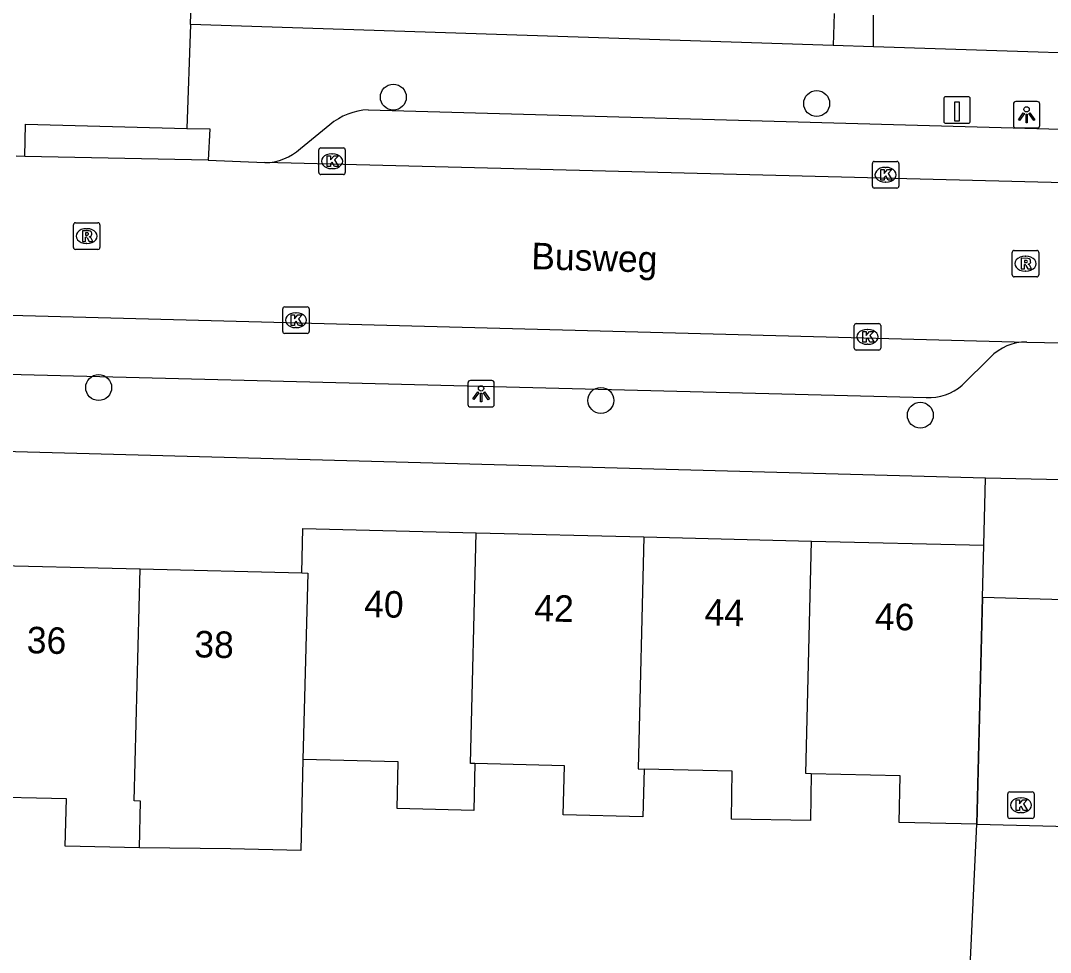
# Model space of a CAD drawing. Extents: x 162082 to 163393, y 388091 to 388632.
# Drawn here: x 162430.78 to 162469.63, y 388296.46 to 388331.61 of the extents above; entities that cross this region are included whole.
import ezdxf

# ---------------------------------------------------------------- set-up
doc = ezdxf.new("R2010")
doc.units = 0
for name, color, linetype in [('IMGEO_Boom', 7, 'Continuous'), ('IMGEO_Kolk', 7, 'Continuous'), ('IMGEO_Laadpaal', 7, 'Continuous'), ('IMGEO_Lichtpunt', 7, 'Continuous'), ('IMGEO_Muur', 7, 'Continuous'), ('IMGEO_Openbare_ruimte_label', 7, 'Continuous'), ('IMGEO_Pand', 7, 'Continuous'), ('IMGEO_Pand_nummerreeks', 7, 'Continuous'), ('IMGEO_Pand_overbouw', 7, 'Continuous'), ('IMGEO_Rijbaan_lokaal_open', 7, 'Continuous'), ('IMGEO_Rioolput', 7, 'Continuous'), ('IMGEO_Voetpad_open', 7, 'Continuous')]:
    doc.layers.add(name, color=color, linetype=linetype)

msp = doc.modelspace()

# ---------------------------------------------------------------- linework, layer by layer
at = {"layer": 'IMGEO_Boom'}
for centre in [(162444.844, 388328.725), (162460.816, 388328.485), (162433.728, 388317.767), (162452.674, 388317.284), (162464.726, 388316.726)]:
    msp.add_circle(centre, 0.489, dxfattribs=at)
at = {"layer": 'IMGEO_Kolk'}
for p, q in [((162442.032, 388325.881), (162442.032, 388326.733)), ((162442.107, 388326.807), (162442.959, 388326.807)), ((162443.033, 388326.733), (162443.033, 388325.881)), ((162442.52, 388326.587), (162442.545, 388326.587)), ((162462.991, 388326.297), (162463.843, 388326.297)), ((162442.543, 388326.027), (162442.518, 388326.027)), ((162462.916, 388325.371), (162462.916, 388326.223)), ((162463.404, 388326.077), (162463.429, 388326.077)), ((162463.917, 388326.223), (162463.917, 388325.371)), ((162442.959, 388325.807), (162442.107, 388325.807)), ((162463.843, 388325.297), (162462.991, 388325.297)), ((162463.427, 388325.517), (162463.402, 388325.517)), ((162440.671, 388319.884), (162440.671, 388320.736)), ((162440.746, 388320.81), (162441.598, 388320.81)), ((162441.159, 388320.59), (162441.184, 388320.59)), ((162441.672, 388320.736), (162441.672, 388319.884)), ((162462.234, 388319.254), (162462.234, 388320.106)), ((162462.309, 388320.18), (162463.161, 388320.18)), ((162463.235, 388320.106), (162463.235, 388319.254)), ((162441.598, 388319.81), (162440.746, 388319.81)), ((162441.182, 388320.03), (162441.157, 388320.03)), ((162462.722, 388319.96), (162462.747, 388319.96)), ((162462.745, 388319.4), (162462.72, 388319.4)), ((162463.161, 388319.18), (162462.309, 388319.18)), ((162468.023, 388301.586), (162468.023, 388302.438)), ((162468.098, 388302.512), (162468.95, 388302.512)), ((162468.511, 388302.292), (162468.536, 388302.292)), ((162469.024, 388302.438), (162469.024, 388301.586)), ((162468.95, 388301.512), (162468.098, 388301.512)), ((162468.534, 388301.732), (162468.509, 388301.732))]:
    msp.add_line(p, q, dxfattribs=at)
for points in [[(162442.032, 388325.881), (162442.032, 388326.733)], [(162442.107, 388326.807), (162442.959, 388326.807)], [(162443.033, 388326.733), (162443.033, 388325.881)], [(162442.353, 388326.507), (162442.476, 388326.507), (162442.476, 388326.356), (162442.606, 388326.507), (162442.77, 388326.507), (162442.624, 388326.356), (162442.777, 388326.107), (162442.625, 388326.107), (162442.54, 388326.271), (162442.476, 388326.204), (162442.476, 388326.107), (162442.353, 388326.107), (162442.353, 388326.507)], [(162462.991, 388326.297), (162463.843, 388326.297)], [(162462.916, 388325.371), (162462.916, 388326.223)], [(162463.237, 388325.997), (162463.36, 388325.997), (162463.36, 388325.846), (162463.49, 388325.997), (162463.654, 388325.997), (162463.508, 388325.846), (162463.661, 388325.597), (162463.509, 388325.597), (162463.424, 388325.761), (162463.36, 388325.694), (162463.36, 388325.597), (162463.237, 388325.597), (162463.237, 388325.997)], [(162463.917, 388326.223), (162463.917, 388325.371)], [(162442.959, 388325.807), (162442.107, 388325.807)], [(162463.843, 388325.297), (162462.991, 388325.297)], [(162440.671, 388319.884), (162440.671, 388320.736)], [(162440.746, 388320.81), (162441.598, 388320.81)], [(162440.992, 388320.51), (162441.115, 388320.51), (162441.115, 388320.359), (162441.245, 388320.51), (162441.409, 388320.51), (162441.263, 388320.359), (162441.416, 388320.11), (162441.264, 388320.11), (162441.179, 388320.274), (162441.115, 388320.207), (162441.115, 388320.11), (162440.992, 388320.11), (162440.992, 388320.51)], [(162441.672, 388320.736), (162441.672, 388319.884)], [(162462.234, 388319.254), (162462.234, 388320.106)], [(162462.309, 388320.18), (162463.161, 388320.18)], [(162463.235, 388320.106), (162463.235, 388319.254)], [(162441.598, 388319.81), (162440.746, 388319.81)], [(162462.555, 388319.88), (162462.678, 388319.88), (162462.678, 388319.729), (162462.808, 388319.88), (162462.972, 388319.88), (162462.826, 388319.729), (162462.979, 388319.48), (162462.827, 388319.48), (162462.742, 388319.644), (162462.678, 388319.577), (162462.678, 388319.48), (162462.555, 388319.48), (162462.555, 388319.88)], [(162463.161, 388319.18), (162462.309, 388319.18)], [(162468.023, 388301.586), (162468.023, 388302.438)], [(162468.098, 388302.512), (162468.95, 388302.512)], [(162468.344, 388302.212), (162468.467, 388302.212), (162468.467, 388302.061), (162468.597, 388302.212), (162468.761, 388302.212), (162468.615, 388302.061), (162468.768, 388301.812), (162468.616, 388301.812), (162468.531, 388301.976), (162468.467, 388301.909), (162468.467, 388301.812), (162468.344, 388301.812), (162468.344, 388302.212)], [(162469.024, 388302.438), (162469.024, 388301.586)], [(162468.95, 388301.512), (162468.098, 388301.512)]]:
    msp.add_lwpolyline(points, dxfattribs=at)
for centre, start, end in [((162442.109, 388326.731), 91.552, 178.448), ((162442.109, 388326.731), 91.552, 178.448), ((162442.957, 388326.731), 1.552, 88.448), ((162442.957, 388326.731), 1.552, 88.448), ((162462.993, 388326.221), 91.552, 178.448), ((162462.993, 388326.221), 91.552, 178.448), ((162463.841, 388326.221), 1.552, 88.448), ((162463.841, 388326.221), 1.552, 88.448), ((162442.109, 388325.883), 181.552, 268.448), ((162442.109, 388325.883), 181.552, 268.448), ((162442.957, 388325.883), 271.552, 358.448), ((162442.957, 388325.883), 271.552, 358.448), ((162462.993, 388325.373), 181.552, 268.448), ((162462.993, 388325.373), 181.552, 268.448), ((162463.841, 388325.373), 271.552, 358.448), ((162463.841, 388325.373), 271.552, 358.448), ((162440.748, 388320.734), 91.552, 178.448), ((162440.748, 388320.734), 91.552, 178.448), ((162441.596, 388320.734), 1.552, 88.448), ((162441.596, 388320.734), 1.552, 88.448), ((162462.311, 388320.104), 91.552, 178.448), ((162462.311, 388320.104), 91.552, 178.448), ((162463.159, 388320.104), 1.552, 88.448), ((162463.159, 388320.104), 1.552, 88.448), ((162440.748, 388319.886), 181.552, 268.448), ((162440.748, 388319.886), 181.552, 268.448), ((162441.596, 388319.886), 271.552, 358.448), ((162441.596, 388319.886), 271.552, 358.448), ((162462.311, 388319.256), 181.552, 268.448), ((162462.311, 388319.256), 181.552, 268.448), ((162463.159, 388319.256), 271.552, 358.448), ((162463.159, 388319.256), 271.552, 358.448), ((162468.1, 388302.436), 91.552, 178.448), ((162468.1, 388302.436), 91.552, 178.448), ((162468.948, 388302.436), 1.552, 88.448), ((162468.948, 388302.436), 1.552, 88.448), ((162468.1, 388301.588), 181.552, 268.448), ((162468.1, 388301.588), 181.552, 268.448), ((162468.948, 388301.588), 271.552, 358.448), ((162468.948, 388301.588), 271.552, 358.448)]:
    msp.add_arc(centre, 0.0765, start, end, dxfattribs=at)
for centre, major_axis, ratio, start_param, end_param in [((162442.519, 388326.307), (-0.387, 0.002), 0.722429, 4.712389, 7.853982), ((162442.544, 388326.307), (-0.39, 0.002), 0.717154, 1.570796, 4.712389), ((162463.403, 388325.797), (-0.387, 0.002), 0.722429, 4.712389, 7.853982), ((162463.428, 388325.797), (-0.39, 0.002), 0.717154, 1.570796, 4.712389), ((162441.158, 388320.31), (-0.387, 0.002), 0.722429, 4.712389, 7.853982), ((162441.183, 388320.31), (-0.39, 0.002), 0.717154, 1.570796, 4.712389), ((162462.721, 388319.68), (-0.387, 0.002), 0.722429, 4.712389, 7.853982), ((162462.746, 388319.68), (-0.39, 0.002), 0.717154, 1.570796, 4.712389), ((162468.51, 388302.012), (-0.387, 0.002), 0.722429, 4.712389, 7.853982), ((162468.535, 388302.012), (-0.39, 0.002), 0.717154, 1.570796, 4.712389)]:
    msp.add_ellipse(centre, major_axis=major_axis, ratio=ratio, start_param=start_param, end_param=end_param, dxfattribs=at)
at = {"layer": 'IMGEO_Laadpaal'}
for p, q in [((162465.611, 388328.655), (162465.611, 388327.814)), ((162465.611, 388328.655), (162465.611, 388327.814)), ((162466.527, 388328.739), (162465.686, 388328.739)), ((162466.527, 388328.739), (162465.686, 388328.739)), ((162466.611, 388327.823), (162466.611, 388328.664)), ((162466.611, 388327.823), (162466.611, 388328.664)), ((162465.695, 388327.739), (162466.536, 388327.739)), ((162465.695, 388327.739), (162466.536, 388327.739))]:
    msp.add_line(p, q, dxfattribs=at)
msp.add_lwpolyline([(162466.026, 388328.552), (162466.186, 388328.552), (162466.186, 388327.819), (162466.026, 388327.819), (162466.026, 388328.552)], dxfattribs=at)
for centre, start, end in [((162465.689, 388328.661), 92.4484, 184.2845), ((162465.689, 388328.661), 92.4484, 184.2845), ((162466.533, 388328.661), 2.4484, 94.2845), ((162466.533, 388328.661), 2.4484, 94.2845), ((162465.689, 388327.817), 182.4484, 274.2845), ((162465.689, 388327.817), 182.4484, 274.2845), ((162466.533, 388327.817), 272.4484, 4.2845), ((162466.533, 388327.817), 272.4484, 4.2845)]:
    msp.add_arc(centre, 0.0779, start, end, dxfattribs=at)
at = {"layer": 'IMGEO_Lichtpunt'}
for p, q in [((162468.238, 388328.467), (162468.238, 388327.66)), ((162468.238, 388328.467), (162468.238, 388327.66)), ((162469.14, 388328.562), (162468.332, 388328.562)), ((162469.14, 388328.562), (162468.332, 388328.562)), ((162469.234, 388327.66), (162469.234, 388328.467)), ((162469.234, 388327.66), (162469.234, 388328.467)), ((162468.332, 388327.566), (162469.14, 388327.566)), ((162468.332, 388327.566), (162469.14, 388327.566)), ((162447.656, 388317.938), (162447.656, 388317.131)), ((162447.656, 388317.938), (162447.656, 388317.131)), ((162448.558, 388318.033), (162447.75, 388318.033)), ((162448.558, 388318.033), (162447.75, 388318.033)), ((162448.652, 388317.131), (162448.652, 388317.938)), ((162448.652, 388317.131), (162448.652, 388317.938)), ((162447.75, 388317.037), (162448.558, 388317.037)), ((162447.75, 388317.037), (162448.558, 388317.037))]:
    msp.add_line(p, q, dxfattribs=at)
for points in [[(162468.612, 388328.131), (162468.651, 388328.103), (162468.463, 388327.841), (162468.425, 388327.868), (162468.612, 388328.131)], [(162468.714, 388328.083), (162468.761, 388328.083), (162468.761, 388327.761), (162468.714, 388327.761), (162468.714, 388328.083)], [(162468.824, 388328.103), (162468.862, 388328.13), (162469.049, 388327.868), (162469.01, 388327.84), (162468.824, 388328.103)], [(162448.03, 388317.602), (162448.069, 388317.574), (162447.881, 388317.312), (162447.843, 388317.339), (162448.03, 388317.602)], [(162448.132, 388317.554), (162448.179, 388317.554), (162448.179, 388317.232), (162448.132, 388317.232), (162448.132, 388317.554)], [(162448.242, 388317.574), (162448.28, 388317.601), (162448.467, 388317.339), (162448.428, 388317.311), (162448.242, 388317.574)]]:
    msp.add_lwpolyline(points, dxfattribs=at)
for centre in [(162468.737, 388328.265), (162448.155, 388317.736)]:
    msp.add_circle(centre, 0.0994, dxfattribs=at)
for centre, start, end in [((162468.332, 388328.467), 90, 180), ((162468.332, 388328.467), 90, 180), ((162469.14, 388328.467), 0, 90), ((162469.14, 388328.467), 0, 90), ((162468.332, 388327.66), 180, 270), ((162468.332, 388327.66), 180, 270), ((162469.14, 388327.66), 270, 0), ((162469.14, 388327.66), 270, 360), ((162447.75, 388317.938), 90, 180), ((162447.75, 388317.938), 90, 180), ((162448.558, 388317.938), 0, 90), ((162448.558, 388317.938), 0, 90), ((162447.75, 388317.131), 180, 270), ((162447.75, 388317.131), 180, 270), ((162448.558, 388317.131), 270, 0), ((162448.558, 388317.131), 270, 360)]:
    msp.add_arc(centre, 0.0946, start, end, dxfattribs=at)
at = {"layer": 'IMGEO_Muur'}
msp.add_lwpolyline([(162466.603, 388295.92), (162466.861, 388301.293)], dxfattribs=at)
at = {"layer": 'IMGEO_Pand'}
for points in [[(162441.388, 388310.774), (162441.429, 388312.454), (162447.975, 388312.292)], [(162447.921, 388303.581), (162447.758, 388303.585), (162447.975, 388312.292)], [(162447.975, 388312.292), (162454.298, 388312.135)], [(162454.298, 388312.135), (162454.08, 388303.378), (162454.304, 388303.372)], [(162454.298, 388312.135), (162460.621, 388311.979)], [(162460.602, 388303.199), (162460.403, 388303.204), (162460.621, 388311.979)], [(162460.621, 388311.979), (162467.122, 388311.818)], [(162466.861, 388301.293), (162467.073, 388309.842), (162467.122, 388311.818)], [(162428.957, 388311.082), (162435.287, 388310.925)], [(162435.265, 388300.402), (162435.308, 388302.169), (162435.07, 388302.175), (162435.287, 388310.925)], [(162435.287, 388310.925), (162441.388, 388310.774)], [(162441.388, 388310.774), (162441.613, 388310.769), (162441.435, 388303.738)], [(162441.435, 388303.738), (162441.35, 388300.301), (162438.703, 388300.367), (162435.265, 388300.402)], [(162447.921, 388303.581), (162447.877, 388301.814), (162444.984, 388301.885), (162445.028, 388303.649), (162441.435, 388303.738)], [(162454.304, 388303.372), (162454.259, 388301.579), (162451.25, 388301.653), (162451.296, 388303.498), (162447.921, 388303.581)], [(162460.602, 388303.199), (162460.582, 388301.439), (162457.608, 388301.486), (162457.624, 388303.29), (162454.304, 388303.372)], [(162466.861, 388301.293), (162463.927, 388301.365), (162463.971, 388303.116), (162460.602, 388303.199)], [(162435.265, 388300.402), (162432.469, 388300.471), (162432.513, 388302.247), (162429.089, 388302.332)]]:
    msp.add_lwpolyline(points, dxfattribs=at)
at = {"layer": 'IMGEO_Pand_overbouw'}
msp.add_lwpolyline([(162470.337, 388301.204), (162470.557, 388309.753), (162467.073, 388309.842), (162466.861, 388301.293)], close=True, dxfattribs=at)
at = {"layer": 'IMGEO_Rijbaan_lokaal_open'}
for points in [[(162430.947, 388326.484), (162430.617, 388326.496)], [(162437.864, 388326.35), (162430.947, 388326.484)], [(162437.864, 388326.35), (162439.995, 388326.254)], [(162473.121, 388325.423), (162439.995, 388326.254)], [(162408.612, 388321.073), (162468.742, 388319.487)], [(162468.742, 388319.487), (162472.729, 388319.405)]]:
    msp.add_lwpolyline(points, dxfattribs=at)
at = {"layer": 'IMGEO_Rioolput'}
for p, q in [((162432.85, 388323.983), (162433.702, 388323.983)), ((162432.775, 388323.057), (162432.775, 388323.909)), ((162433.263, 388323.763), (162433.288, 388323.763)), ((162433.776, 388323.909), (162433.776, 388323.057)), ((162433.286, 388323.203), (162433.261, 388323.203)), ((162433.702, 388322.983), (162432.85, 388322.983)), ((162468.193, 388322.018), (162468.193, 388322.87)), ((162468.268, 388322.944), (162469.12, 388322.944)), ((162469.194, 388322.87), (162469.194, 388322.018)), ((162468.681, 388322.724), (162468.706, 388322.724)), ((162468.704, 388322.164), (162468.679, 388322.164)), ((162469.12, 388321.944), (162468.268, 388321.944))]:
    msp.add_line(p, q, dxfattribs=at)
for points in [[(162432.85, 388323.983), (162433.702, 388323.983)], [(162432.775, 388323.057), (162432.775, 388323.909)], [(162433.364, 388323.681), (162433.112, 388323.683), (162433.112, 388323.283)], [(162433.29, 388323.602), (162433.236, 388323.602), (162433.236, 388323.521)], [(162433.776, 388323.909), (162433.776, 388323.057)], [(162433.112, 388323.283), (162433.236, 388323.283), (162433.236, 388323.445), (162433.247, 388323.445)], [(162433.236, 388323.521), (162433.288, 388323.521)], [(162433.294, 388323.416), (162433.365, 388323.283), (162433.505, 388323.283), (162433.44, 388323.409)], [(162433.702, 388322.983), (162432.85, 388322.983)], [(162468.193, 388322.018), (162468.193, 388322.87)], [(162468.268, 388322.944), (162469.12, 388322.944)], [(162469.194, 388322.87), (162469.194, 388322.018)], [(162468.782, 388322.642), (162468.53, 388322.644), (162468.53, 388322.244)], [(162468.708, 388322.563), (162468.654, 388322.563), (162468.654, 388322.482)], [(162468.654, 388322.482), (162468.706, 388322.482)], [(162468.53, 388322.244), (162468.654, 388322.244), (162468.654, 388322.406), (162468.665, 388322.406)], [(162468.712, 388322.377), (162468.783, 388322.244), (162468.923, 388322.244), (162468.858, 388322.37)], [(162469.12, 388321.944), (162468.268, 388321.944)]]:
    msp.add_lwpolyline(points, dxfattribs=at)
for centre, radius, start, end in [((162432.852, 388323.907), 0.0765, 91.552, 178.448), ((162432.852, 388323.907), 0.0765, 91.552, 178.448), ((162433.7, 388323.907), 0.0765, 1.552, 88.448), ((162433.7, 388323.907), 0.0765, 1.552, 88.448), ((162433.296, 388323.506), 0.0964, 77.0061, 93.1865), ((162433.31, 388323.563), 0.0378, 276.6634, 79.6772), ((162433.363, 388323.571), 0.109, 350.3612, 89.416), ((162433.246, 388323.392), 0.0533, 26.0293, 88.6989), ((162433.272, 388323.71), 0.19, 274.7715, 282.9687), ((162433.361, 388323.571), 0.112, 277.5842, 350.9817), ((162433.345, 388323.356), 0.108, 29.5134, 73.7905), ((162432.852, 388323.059), 0.0765, 181.552, 268.448), ((162432.852, 388323.059), 0.0765, 181.552, 268.448), ((162433.7, 388323.059), 0.0765, 271.552, 358.448), ((162433.7, 388323.059), 0.0765, 271.552, 358.448), ((162468.27, 388322.868), 0.0765, 91.552, 178.448), ((162468.27, 388322.868), 0.0765, 91.552, 178.448), ((162469.118, 388322.868), 0.0765, 1.552, 88.448), ((162469.118, 388322.868), 0.0765, 1.552, 88.448), ((162468.69, 388322.671), 0.19, 274.7715, 282.9687), ((162468.714, 388322.467), 0.0964, 77.0061, 93.1865), ((162468.728, 388322.524), 0.0378, 276.6634, 79.6772), ((162468.781, 388322.532), 0.109, 350.3612, 89.416), ((162468.779, 388322.532), 0.112, 277.5842, 350.9817), ((162468.763, 388322.317), 0.108, 29.5134, 73.7905), ((162468.664, 388322.353), 0.0533, 26.0293, 88.6989), ((162468.27, 388322.02), 0.0765, 181.552, 268.448), ((162468.27, 388322.02), 0.0765, 181.552, 268.448), ((162469.118, 388322.02), 0.0765, 271.552, 358.448), ((162469.118, 388322.02), 0.0765, 271.552, 358.448)]:
    msp.add_arc(centre, radius, start, end, dxfattribs=at)
for centre, major_axis, ratio, start_param, end_param in [((162433.262, 388323.483), (-0.387, 0.002), 0.722429, 4.712389, 7.853982), ((162433.287, 388323.483), (-0.39, 0.002), 0.717154, 1.570796, 4.712389), ((162468.68, 388322.444), (-0.387, 0.002), 0.722429, 4.712389, 7.853982), ((162468.705, 388322.444), (-0.39, 0.002), 0.717154, 1.570796, 4.712389)]:
    msp.add_ellipse(centre, major_axis=major_axis, ratio=ratio, start_param=start_param, end_param=end_param, dxfattribs=at)
at = {"layer": 'IMGEO_Voetpad_open'}
for points in [[(162437.193, 388331.464), (162437.393, 388338.278)], [(162461.481, 388331.883), (162461.443, 388330.674)], [(162462.963, 388330.625), (162462.96, 388331.824)], [(162437.193, 388331.464), (162437.056, 388327.547)], [(162461.443, 388330.674), (162437.193, 388331.464)], [(162462.963, 388330.625), (162461.443, 388330.674)], [(162489.342, 388329.766), (162462.963, 388330.625)], [(162443.895, 388328.247), (162472.278, 388327.452), (162472.275, 388326.347)], [(162430.947, 388326.484), (162430.97, 388327.708), (162437.056, 388327.547)], [(162437.056, 388327.547), (162437.924, 388327.524), (162437.864, 388326.35)], [(162441.339, 388326.789), (162442.445, 388327.687)], [(162412.486, 388318.729), (162464.943, 388317.394)], [(162466.311, 388317.858), (162467.363, 388318.906)], [(162467.185, 388314.347), (162402.771, 388316.096)], [(162467.122, 388311.818), (162467.185, 388314.347)], [(162470.635, 388314.273), (162467.185, 388314.347)], [(162464.828, 388293.154), (162466.536, 388293.14), (162466.603, 388295.92), (162466.861, 388301.293)]]:
    msp.add_lwpolyline(points, dxfattribs=at)
for centre, radius, start, end in [((162444.031, 388325.736), 2.514, 93.1119, 129.1219), ((162439.988, 388328.227), 1.973, 270.2055, 313.2061), ((162468.732, 388317.584), 1.903, 89.6941, 135.9992), ((162465.07, 388319.267), 1.877, 266.1068, 311.3651)]:
    msp.add_arc(centre, radius, start, end, dxfattribs=at)

# ---------------------------------------------------------------- texts
at = {"layer": 'IMGEO_Openbare_ruimte_label'}
msp.add_text('Busweg', height=1, rotation=358.3389, dxfattribs=at).set_placement((162450.038, 388322.238))
at = {"layer": 'IMGEO_Pand_nummerreeks'}
for s, rotation, p in [('40', 358.582, (162443.736, 388309.116)), ('42', 358.582, (162450.153, 388308.957)), ('44', 358.582, (162456.579, 388308.798)), ('46', 358.582, (162463.003, 388308.639)), ('36', 358.582, (162431.007, 388307.75)), ('38', 358.5848, (162437.327, 388307.594))]:
    msp.add_text(s, height=1, rotation=rotation, dxfattribs=at).set_placement(p)

doc.saveas('drawing.dxf')
